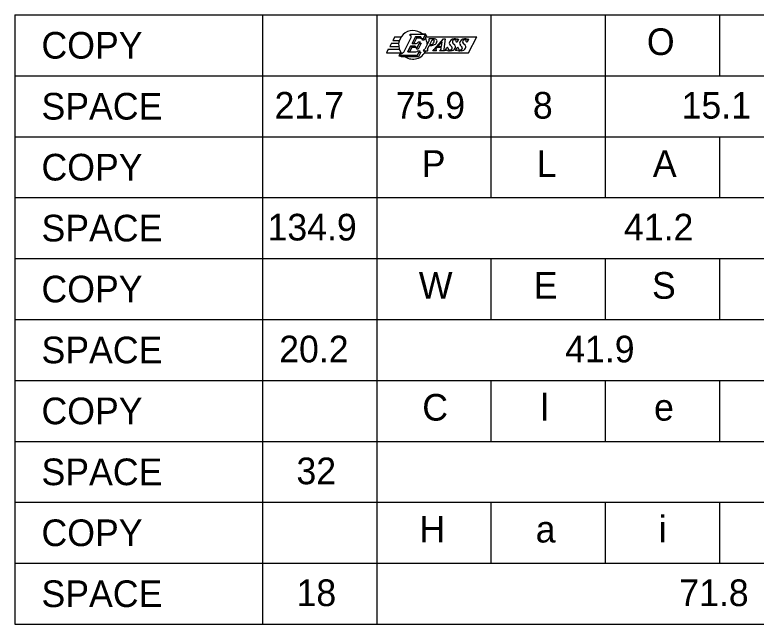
# Model space of a CAD drawing. Extents: x 10268259 to 10268554, y 2141099 to 2141249.
# Drawn here: x 10268395.48 to 10268414.94, y 2141109.03 to 2141125.03 of the extents above; entities that cross this region are included whole.
import ezdxf

# ---------------------------------------------------------------- set-up
doc = ezdxf.new("R2010")
doc.units = 0
for name, color, linetype in [('60', 7, 'Continuous'), ('61', 7, 'Continuous'), ('62', 7, 'Continuous'), ('TextMisc', 7, 'Continuous')]:
    doc.layers.add(name, color=color, linetype=linetype)

msp = doc.modelspace()

# ---------------------------------------------------------------- linework, layer by layer
at = {"layer": '60'}
for p, q in [((10268395.48, 2141125.028), (10268470.98, 2141125.028)), ((10268395.48, 2141125.028), (10268395.48, 2141109.028)), ((10268401.98, 2141125.028), (10268401.98, 2141109.028)), ((10268404.98, 2141125.028), (10268404.98, 2141109.028)), ((10268407.98, 2141125.028), (10268407.98, 2141121.828)), ((10268410.98, 2141125.028), (10268410.98, 2141121.828)), ((10268413.98, 2141125.028), (10268413.98, 2141123.428)), ((10268395.48, 2141121.828), (10268470.98, 2141121.828)), ((10268407.98, 2141121.828), (10268407.98, 2141120.228)), ((10268410.98, 2141121.828), (10268410.98, 2141120.228)), ((10268413.98, 2141121.828), (10268413.98, 2141120.228)), ((10268395.48, 2141118.628), (10268470.98, 2141118.628)), ((10268407.98, 2141118.628), (10268407.98, 2141117.028)), ((10268410.98, 2141118.628), (10268410.98, 2141117.028)), ((10268413.98, 2141118.628), (10268413.98, 2141117.028)), ((10268395.48, 2141115.428), (10268470.98, 2141115.428)), ((10268407.98, 2141115.428), (10268407.98, 2141113.828)), ((10268410.98, 2141115.428), (10268410.98, 2141113.828)), ((10268413.98, 2141115.428), (10268413.98, 2141113.828)), ((10268395.48, 2141112.228), (10268470.98, 2141112.228)), ((10268407.98, 2141112.228), (10268407.98, 2141110.628)), ((10268410.98, 2141112.228), (10268410.98, 2141110.628)), ((10268413.98, 2141112.228), (10268413.98, 2141110.628)), ((10268395.48, 2141109.028), (10268470.98, 2141109.028))]:
    msp.add_line(p, q, dxfattribs=at)
at = {"layer": '61'}
for p, q in [((10268395.48, 2141123.428), (10268470.98, 2141123.428)), ((10268395.48, 2141120.228), (10268470.98, 2141120.228)), ((10268395.48, 2141117.028), (10268470.98, 2141117.028)), ((10268395.48, 2141113.828), (10268470.98, 2141113.828)), ((10268395.48, 2141110.628), (10268470.98, 2141110.628))]:
    msp.add_line(p, q, dxfattribs=at)
at = {"layer": '62'}
for p, q in [((10268405.846, 2141124.49), (10268405.862, 2141124.522)), ((10268405.862, 2141124.522), (10268406.26, 2141124.522)), ((10268406.174, 2141124.525), (10268406.266, 2141124.525)), ((10268406.26, 2141124.522), (10268406.196, 2141124.396)), ((10268406.196, 2141124.396), (10268406.242, 2141124.486)), ((10268406.196, 2141124.396), (10268406.242, 2141124.486)), ((10268406.29, 2141124.486), (10268406.226, 2141124.361)), ((10268406.29, 2141124.486), (10268406.226, 2141124.361)), ((10268406.242, 2141124.486), (10268406.29, 2141124.486)), ((10268406.242, 2141124.486), (10268406.29, 2141124.486)), ((10268406.266, 2141124.525), (10268406.246, 2141124.486)), ((10268405.452, 2141124.451), (10268405.404, 2141124.357)), ((10268405.404, 2141124.357), (10268405.574, 2141124.357)), ((10268405.452, 2141124.451), (10268405.62, 2141124.451)), ((10268405.688, 2141124.052), (10268405.883, 2141124.434)), ((10268405.997, 2141124.451), (10268405.907, 2141124.275)), ((10268405.907, 2141124.275), (10268405.997, 2141124.451)), ((10268405.907, 2141124.275), (10268405.997, 2141124.451)), ((10268406.026, 2141124.416), (10268405.954, 2141124.275)), ((10268406.026, 2141124.416), (10268405.954, 2141124.275)), ((10268406.116, 2141124.451), (10268405.997, 2141124.451)), ((10268405.997, 2141124.451), (10268406.116, 2141124.451)), ((10268405.997, 2141124.451), (10268406.116, 2141124.451)), ((10268406.154, 2141124.416), (10268406.026, 2141124.416)), ((10268406.154, 2141124.416), (10268406.026, 2141124.416)), ((10268406.119, 2141124.322), (10268406.035, 2141124.158)), ((10268406.061, 2141124.301), (10268406.072, 2141124.322)), ((10268406.072, 2141124.322), (10268406.119, 2141124.322)), ((10268406.196, 2141124.396), (10268406.149, 2141124.396)), ((10268406.179, 2141124.396), (10268406.196, 2141124.396)), ((10268406.179, 2141124.396), (10268406.196, 2141124.396)), ((10268406.226, 2141124.361), (10268406.179, 2141124.361)), ((10268406.226, 2141124.361), (10268406.179, 2141124.361)), ((10268406.355, 2141124.354), (10268406.239, 2141124.126)), ((10268406.272, 2141124.451), (10268407.609, 2141124.451)), ((10268406.355, 2141124.398), (10268406.348, 2141124.386)), ((10268406.498, 2141124.398), (10268406.355, 2141124.398)), ((10268406.373, 2141124.245), (10268406.439, 2141124.375)), ((10268406.439, 2141124.375), (10268406.462, 2141124.375)), ((10268406.495, 2141124.123), (10268406.734, 2141124.398)), ((10268406.695, 2141124.318), (10268406.588, 2141124.194)), ((10268406.679, 2141124.194), (10268406.695, 2141124.318)), ((10268406.734, 2141124.398), (10268406.776, 2141124.398)), ((10268406.776, 2141124.398), (10268406.741, 2141124.129)), ((10268407.013, 2141124.398), (10268407.022, 2141124.398)), ((10268407.028, 2141124.375), (10268407.018, 2141124.375)), ((10268407.088, 2141124.314), (10268407.076, 2141124.314)), ((10268407.125, 2141124.387), (10268407.088, 2141124.314)), ((10268407.107, 2141124.387), (10268407.125, 2141124.387)), ((10268407.283, 2141124.398), (10268407.292, 2141124.398)), ((10268407.298, 2141124.375), (10268407.288, 2141124.375)), ((10268407.357, 2141124.314), (10268407.345, 2141124.314)), ((10268407.394, 2141124.387), (10268407.357, 2141124.314)), ((10268407.377, 2141124.387), (10268407.394, 2141124.387)), ((10268407.394, 2141124.029), (10268407.609, 2141124.451)), ((10268405.285, 2141124.123), (10268405.237, 2141124.029)), ((10268405.285, 2141124.123), (10268405.574, 2141124.123)), ((10268405.369, 2141124.287), (10268405.321, 2141124.193)), ((10268405.321, 2141124.193), (10268405.558, 2141124.193)), ((10268405.369, 2141124.287), (10268405.558, 2141124.287)), ((10268405.871, 2141124.205), (10268405.794, 2141124.053)), ((10268405.794, 2141124.053), (10268405.871, 2141124.205)), ((10268405.794, 2141124.053), (10268405.871, 2141124.205)), ((10268405.901, 2141124.17), (10268405.841, 2141124.053)), ((10268405.901, 2141124.17), (10268405.841, 2141124.053)), ((10268405.974, 2141124.205), (10268405.871, 2141124.205)), ((10268405.871, 2141124.205), (10268405.97, 2141124.205)), ((10268405.871, 2141124.205), (10268405.97, 2141124.205)), ((10268406.004, 2141124.169), (10268405.901, 2141124.17)), ((10268406.004, 2141124.169), (10268405.901, 2141124.17)), ((10268405.907, 2141124.275), (10268406.019, 2141124.275)), ((10268405.954, 2141124.275), (10268405.907, 2141124.275)), ((10268405.954, 2141124.275), (10268405.907, 2141124.275)), ((10268406.035, 2141124.158), (10268406, 2141124.158)), ((10268406.028, 2141124.158), (10268406.035, 2141124.158)), ((10268406.028, 2141124.158), (10268406.035, 2141124.158)), ((10268406.065, 2141124.123), (10268406.029, 2141124.123)), ((10268406.065, 2141124.123), (10268406.029, 2141124.123)), ((10268406.035, 2141124.158), (10268406.101, 2141124.287)), ((10268406.035, 2141124.158), (10268406.101, 2141124.287)), ((10268406.148, 2141124.287), (10268406.065, 2141124.123)), ((10268406.148, 2141124.287), (10268406.065, 2141124.123)), ((10268406.101, 2141124.287), (10268406.148, 2141124.287)), ((10268406.101, 2141124.287), (10268406.148, 2141124.287)), ((10268406.211, 2141124.103), (10268406.2, 2141124.082)), ((10268406.313, 2141124.126), (10268406.361, 2141124.221)), ((10268406.317, 2141124.082), (10268406.324, 2141124.094)), ((10268406.361, 2141124.221), (10268406.396, 2141124.221)), ((10268406.396, 2141124.245), (10268406.373, 2141124.245)), ((10268406.452, 2141124.082), (10268406.462, 2141124.102)), ((10268406.567, 2141124.171), (10268406.533, 2141124.132)), ((10268406.552, 2141124.095), (10268406.545, 2141124.082)), ((10268406.676, 2141124.171), (10268406.567, 2141124.171)), ((10268406.588, 2141124.194), (10268406.679, 2141124.194)), ((10268406.632, 2141124.082), (10268406.643, 2141124.102)), ((10268406.671, 2141124.129), (10268406.676, 2141124.171)), ((10268406.756, 2141124.094), (10268406.75, 2141124.082)), ((10268406.776, 2141124.088), (10268406.819, 2141124.171)), ((10268406.819, 2141124.171), (10268406.837, 2141124.171)), ((10268406.902, 2141124.105), (10268406.915, 2141124.105)), ((10268406.948, 2141124.185), (10268406.906, 2141124.228)), ((10268406.981, 2141124.285), (10268407.03, 2141124.236)), ((10268407.046, 2141124.088), (10268407.088, 2141124.171)), ((10268407.088, 2141124.171), (10268407.107, 2141124.171)), ((10268407.172, 2141124.105), (10268407.184, 2141124.105)), ((10268407.217, 2141124.185), (10268407.175, 2141124.228)), ((10268407.25, 2141124.285), (10268407.3, 2141124.236)), ((10268405.237, 2141124.029), (10268405.62, 2141124.029)), ((10268405.597, 2141124.02), (10268405.561, 2141123.951)), ((10268405.561, 2141123.951), (10268405.635, 2141123.951)), ((10268405.575, 2141123.959), (10268405.601, 2141124.011)), ((10268406.044, 2141123.959), (10268405.575, 2141123.959)), ((10268405.597, 2141124.02), (10268405.626, 2141124.02)), ((10268405.601, 2141124.011), (10268405.621, 2141124.011)), ((10268405.622, 2141123.924), (10268405.64, 2141123.959)), ((10268405.622, 2141123.924), (10268405.64, 2141123.959)), ((10268406.073, 2141123.924), (10268405.622, 2141123.924)), ((10268406.073, 2141123.924), (10268405.622, 2141123.924)), ((10268405.64, 2141123.959), (10268406.044, 2141123.959)), ((10268405.64, 2141123.959), (10268406.044, 2141123.959)), ((10268405.794, 2141124.053), (10268406.009, 2141124.053)), ((10268405.841, 2141124.053), (10268405.794, 2141124.053)), ((10268405.841, 2141124.053), (10268405.794, 2141124.053)), ((10268406.108, 2141124.084), (10268406.044, 2141123.959)), ((10268406.044, 2141123.959), (10268406.09, 2141124.049)), ((10268406.044, 2141123.959), (10268406.09, 2141124.049)), ((10268406.061, 2141124.084), (10268406.108, 2141124.084)), ((10268406.137, 2141124.049), (10268406.073, 2141123.924)), ((10268406.137, 2141124.049), (10268406.073, 2141123.924)), ((10268406.09, 2141124.049), (10268406.137, 2141124.049)), ((10268406.09, 2141124.049), (10268406.137, 2141124.049)), ((10268406.2, 2141124.082), (10268406.317, 2141124.082)), ((10268406.24, 2141124.029), (10268407.394, 2141124.029)), ((10268406.545, 2141124.082), (10268406.452, 2141124.082)), ((10268406.75, 2141124.082), (10268406.632, 2141124.082)), ((10268406.805, 2141124.088), (10268406.776, 2141124.088)), ((10268406.927, 2141124.082), (10268406.892, 2141124.082)), ((10268407.074, 2141124.088), (10268407.046, 2141124.088)), ((10268407.197, 2141124.082), (10268407.162, 2141124.082))]:
    msp.add_line(p, q, dxfattribs=at)
for points in [[(10268406.174, 2141124.525), (10268406.266, 2141124.525), (10268406.246, 2141124.486), (10268406.242, 2141124.486), (10268406.26, 2141124.522), (10268406.178, 2141124.521)], [(10268405.626, 2141124.02), (10268405.597, 2141124.02), (10268405.561, 2141123.951), (10268405.635, 2141123.951), (10268405.64, 2141123.959), (10268405.575, 2141123.959), (10268405.602, 2141124.011), (10268405.621, 2141124.011), (10268405.633, 2141124.012)]]:
    msp.add_lwpolyline(points, close=True, dxfattribs=at)
for centre, radius, start, end in [((10268405.93, 2141124.24), 0.375, 48.5904, 217.4727), ((10268405.848, 2141124.451), 0.0387, 332.9998, 93.8045), ((10268406.019, 2141124.322), 0.0469, 270, 332.9883), ((10268406.116, 2141124.414), 0.0375, 332.2089, 90), ((10268406.116, 2141124.414), 0.0375, 3.5833, 90), ((10268406.116, 2141124.414), 0.0375, 3.5833, 90), ((10268406.146, 2141124.378), 0.0375, 332.2089, 27.9127), ((10268406.146, 2141124.378), 0.0375, 332.2089, 27.9127), ((10268405.93, 2141124.24), 0.375, 2.4236, 29.2771), ((10268406.359, 2141124.381), 0.0117, 152.9784, 231.1602), ((10268406.343, 2141124.36), 0.0141, 333.0027, 51.1602), ((10268406.377, 2141124.357), 0.117, 302.4206, 351.076), ((10268406.462, 2141124.343), 0.0316, 351.076, 90), ((10268406.498, 2141124.332), 0.0668, 29.4315, 90), ((10268406.449, 2141124.351), 0.117, 296.6431, 344.7074), ((10268406.505, 2141124.336), 0.0586, 344.7074, 29.4315), ((10268407.013, 2141124.269), 0.129, 90, 172.3089), ((10268407.018, 2141124.322), 0.0527, 90, 225), ((10268407.022, 2141124.281), 0.117, 64.0896, 90), ((10268407.028, 2141124.34), 0.0352, 345.6915, 90), ((10268407.076, 2141124.328), 0.0141, 165.6915, 270), ((10268407.089, 2141124.418), 0.0352, 244.0896, 292.0347), ((10268407.107, 2141124.373), 0.0141, 90, 112.0347), ((10268407.283, 2141124.269), 0.129, 90, 172.3089), ((10268407.288, 2141124.322), 0.0527, 90, 225), ((10268407.292, 2141124.281), 0.117, 64.0896, 90), ((10268407.298, 2141124.34), 0.0352, 345.6915, 90), ((10268407.346, 2141124.328), 0.0141, 165.6915, 270), ((10268407.358, 2141124.418), 0.0352, 244.0896, 292.0347), ((10268407.377, 2141124.373), 0.0141, 90, 112.0347), ((10268405.974, 2141124.175), 0.0305, 350.3502, 98.3344), ((10268405.974, 2141124.175), 0.0305, 350.3502, 98.3344), ((10268405.974, 2141124.175), 0.0305, 327.421, 90), ((10268406.004, 2141124.139), 0.0305, 327.421, 37.9799), ((10268406.004, 2141124.139), 0.0305, 327.421, 37.9799), ((10268406.231, 2141124.092), 0.0234, 106.4317, 152.9742), ((10268406.218, 2141124.137), 0.0234, 286.4317, 332.9959), ((10268406.323, 2141124.121), 0.0117, 152.9884, 244.7832), ((10268406.313, 2141124.1), 0.0117, 333.0239, 64.7832), ((10268406.396, 2141124.327), 0.0821, 270, 302.4206), ((10268406.396, 2141124.456), 0.234, 270, 296.6431), ((10268406.472, 2141124.097), 0.0117, 102.7162, 153.0239), ((10268406.459, 2141124.154), 0.0469, 282.7162, 318.9966), ((10268406.542, 2141124.124), 0.0117, 138.9824, 268.6869), ((10268406.542, 2141124.101), 0.0117, 332.9784, 88.6869), ((10268406.653, 2141124.097), 0.0117, 99.2397, 153.0239), ((10268406.648, 2141124.132), 0.0234, 279.2397, 352.5632), ((10268406.76, 2141124.126), 0.0188, 172.5884, 241.8673), ((10268406.745, 2141124.099), 0.0117, 332.9784, 61.8673), ((10268406.827, 2141124.064), 0.0328, 64.3795, 133.1892), ((10268406.837, 2141124.16), 0.0117, 358.6664, 90), ((10268406.892, 2141124.199), 0.117, 244.3795, 270), ((10268406.902, 2141124.158), 0.0527, 178.6665, 270), ((10268406.955, 2141124.277), 0.0703, 172.3089, 225), ((10268406.915, 2141124.152), 0.0469, 270, 45), ((10268406.927, 2141124.211), 0.129, 270, 334.95), ((10268406.98, 2141124.186), 0.0703, 334.95, 45), ((10268407.097, 2141124.064), 0.0328, 64.3795, 133.1892), ((10268407.107, 2141124.16), 0.0117, 358.6664, 90), ((10268407.161, 2141124.199), 0.117, 244.3795, 270), ((10268407.172, 2141124.158), 0.0527, 178.6665, 270), ((10268407.225, 2141124.277), 0.0703, 172.3089, 225), ((10268407.184, 2141124.152), 0.0469, 270, 45), ((10268407.197, 2141124.211), 0.129, 270, 334.95), ((10268407.25, 2141124.186), 0.0703, 334.95, 45), ((10268405.621, 2141124.086), 0.075, 270, 332.9991), ((10268405.93, 2141124.24), 0.375, 237.5383, 335.047), ((10268406.009, 2141124.111), 0.0586, 270, 332.5096)]:
    msp.add_arc(centre, radius, start, end, dxfattribs=at)

# ---------------------------------------------------------------- texts
for s, p in [('O', (10268412.072, 2141123.973)), ('21.7', (10268402.299, 2141122.303)), ('75.9', (10268405.478, 2141122.303)), ('8', (10268409.08, 2141122.303)), ('15.1', (10268412.983, 2141122.303)), ('P', (10268406.161, 2141120.773)), ('L', (10268409.182, 2141120.773)), ('A', (10268412.229, 2141120.773)), ('134.9', (10268402.113, 2141119.103)), ('41.2', (10268411.47, 2141119.103)), ('W', (10268406.086, 2141117.573)), ('E', (10268409.103, 2141117.573)), ('S', (10268412.206, 2141117.573)), ('20.2', (10268402.42, 2141115.903)), ('41.9', (10268409.928, 2141115.903)), ('C', (10268406.176, 2141114.373)), ('l', (10268409.284, 2141114.373)), ('e', (10268412.26, 2141114.373)), ('32', (10268402.873, 2141112.703)), ('H', (10268406.1, 2141111.173)), ('i', (10268412.383, 2141111.173)), ('a', (10268409.154, 2141111.173)), ('18', (10268402.875, 2141109.503)), ('71.8', (10268412.922, 2141109.503))]:
    msp.add_text(s, height=0.7, dxfattribs=at).set_placement(p)
at = {"layer": 'TextMisc'}
for s, p in [('COPY', (10268396.18, 2141123.878)), ('SPACE', (10268396.18, 2141122.278)), ('COPY', (10268396.18, 2141120.678)), ('SPACE', (10268396.18, 2141119.078)), ('COPY', (10268396.18, 2141117.478)), ('SPACE', (10268396.18, 2141115.878)), ('COPY', (10268396.18, 2141114.278)), ('SPACE', (10268396.18, 2141112.678)), ('COPY', (10268396.18, 2141111.078)), ('SPACE', (10268396.18, 2141109.478))]:
    msp.add_text(s, height=0.7, dxfattribs=at).set_placement(p)

doc.saveas('drawing.dxf')
